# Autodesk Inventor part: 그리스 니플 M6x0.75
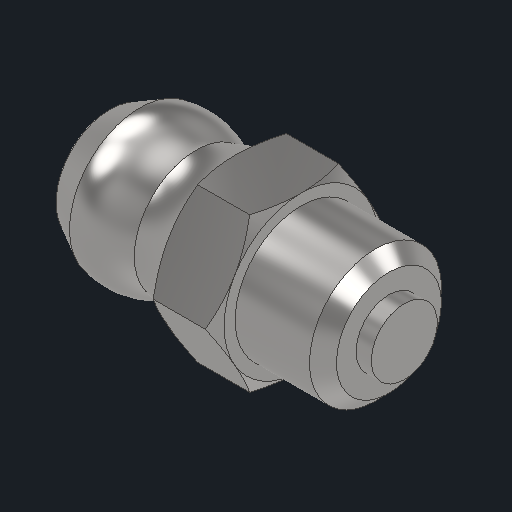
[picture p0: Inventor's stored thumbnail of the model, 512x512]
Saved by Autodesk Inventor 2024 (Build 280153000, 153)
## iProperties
Created: 2025-02
Part Number: 그리스 니플 M6x0.75
Material: 강철, 연강
Description: 윤활 니플, 원추 유형 A
Document SubType Name: Modeling
Designer: kh_501
Density: 7.85 g/cm^3
Appearance: 기본값
Author: jhkim
Sending System: Autodesk Inventor 2025
Preprocessor: ST-DEVELOPER v20
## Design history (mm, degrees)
node "그리스 니플 M6x0.751"
node "솔리드1"
body "Solid1"
